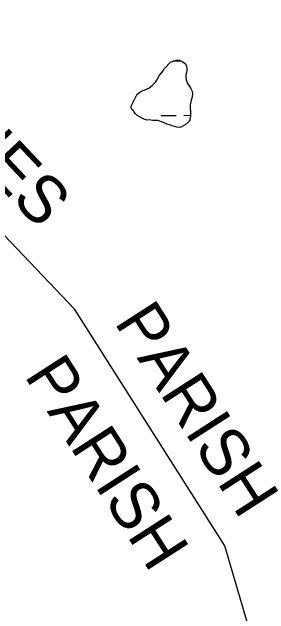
# Model space of a CAD drawing. Extents: x 3702978 to 3741108, y 397120 to 422907.
# Drawn here: x 3709024 to 3709567, y 408927 to 410197 of the extents above; entities that cross this region are included whole.
import ezdxf

# ---------------------------------------------------------------- set-up
doc = ezdxf.new("R2010")
doc.units = 0
for name, color, linetype in [('V-GRID-MAJR', 7, 'Continuous'), ('V-TOPO-BNDY', 7, 'Continuous'), ('V-TOPO-GNAM-IDEN', 7, 'Continuous'), ('V-TOPO-SHOR', 7, 'Continuous'), ('V-WETL-SWMP', 7, 'Continuous')]:
    doc.layers.add(name, color=color, linetype=linetype)

msp = doc.modelspace()

# ---------------------------------------------------------------- linework, layer by layer
at = {"layer": 'V-GRID-MAJR'}
msp.add_spline([(3707136.067, 408587.592), (3709783.788, 408618.69), (3715079.223, 408681.465), (3720374.649, 408745.011), (3725670.066, 408809.326), (3730965.473, 408874.412), (3736260.87, 408940.268), (3738908.566, 408973.485)], degree=3, dxfattribs=at)
at = {"layer": 'V-TOPO-BNDY'}
for p, q in [((3709157.052, 409569.789), (3708437.264, 410322.089)), ((3709474.211, 409070.798), (3709157.052, 409569.789)), ((3709593.302, 408661.849), (3709474.211, 409070.798))]:
    msp.add_line(p, q, dxfattribs=at)
at = {"layer": 'V-TOPO-SHOR'}
msp.add_lwpolyline([(3709275.193, 409997.449), (3709276.507, 410000.198), (3709289.023, 410024.275), (3709294.4, 410028.46), (3709300.47, 410031.977), (3709303.864, 410032.719), (3709313.328, 410036.978), (3709320.724, 410042.563), (3709327.415, 410049.498), (3709330.066, 410053.634), (3709332.061, 410056.396), (3709336.014, 410063.963), (3709340.685, 410069.499), (3709343.349, 410072.954), (3709346.657, 410078.465), (3709359.369, 410091.642), (3709365.452, 410094.477), (3709371.558, 410095.95), (3709378.383, 410095.391), (3709385.257, 410092.107), (3709390.781, 410088.117), (3709392.91, 410083.385), (3709393.652, 410079.991), (3709393.775, 410073.178), (3709393.155, 410069.759), (3709391.878, 410064.966), (3709391.27, 410060.866), (3709392.073, 410054.066), (3709393.497, 410050.684), (3709394.24, 410047.29), (3709397.026, 410043.933), (3709401.236, 410037.193), (3709404.059, 410031.792), (3709405.519, 410026.367), (3709405.58, 410022.96), (3709404.352, 410015.442), (3709403.063, 410011.33), (3709402.443, 410007.911), (3709401.129, 410005.162), (3709400.521, 410001.062), (3709400.681, 409992.205), (3709401.423, 409988.811), (3709401.643, 409976.549), (3709400.366, 409971.755), (3709399.746, 409968.337), (3709397.07, 409965.563), (3709390.367, 409959.309), (3709380.915, 409954.369), (3709377.521, 409953.627), (3709372.74, 409954.222), (3709367.947, 409955.499), (3709362.46, 409957.445), (3709357.654, 409959.403), (3709351.499, 409960.656), (3709344.625, 409963.94), (3709332.276, 409968.488), (3709321.376, 409968.293), (3709314.539, 409969.533), (3709309.77, 409969.447), (3709303.602, 409971.381), (3709296.728, 409974.665), (3709288.468, 409979.287), (3709285, 409982.632), (3709282.214, 409985.989), (3709280.802, 409988.69), (3709278.041, 409990.685)], close=True, dxfattribs=at)
at = {"layer": 'V-WETL-SWMP'}
for p, q in [((3709365.437, 410094.47), (3709379.934, 410094.65)), ((3709339.413, 409978.706), (3709371.411, 409979.103)), ((3709387.41, 409979.302), (3709401.59, 409979.478))]:
    msp.add_line(p, q, dxfattribs=at)
msp.add_lwpolyline([(3709275.193, 409997.449), (3709276.507, 410000.198), (3709289.023, 410024.275), (3709294.4, 410028.46), (3709300.47, 410031.977), (3709303.864, 410032.719), (3709313.328, 410036.978), (3709320.724, 410042.563), (3709327.415, 410049.498), (3709330.066, 410053.634), (3709332.061, 410056.396), (3709336.014, 410063.963), (3709340.685, 410069.499), (3709343.349, 410072.954), (3709346.657, 410078.465), (3709359.369, 410091.642), (3709365.452, 410094.477), (3709371.558, 410095.95), (3709378.383, 410095.391), (3709385.257, 410092.107), (3709390.781, 410088.117), (3709392.91, 410083.385), (3709393.652, 410079.991), (3709393.775, 410073.178), (3709393.155, 410069.759), (3709391.878, 410064.966), (3709391.27, 410060.866), (3709392.073, 410054.066), (3709393.497, 410050.684), (3709394.24, 410047.29), (3709397.026, 410043.933), (3709401.236, 410037.193), (3709404.059, 410031.792), (3709405.519, 410026.367), (3709405.58, 410022.96), (3709404.352, 410015.442), (3709403.063, 410011.33), (3709402.443, 410007.911), (3709401.129, 410005.162), (3709400.521, 410001.062), (3709400.681, 409992.205), (3709401.423, 409988.811), (3709401.643, 409976.549), (3709400.366, 409971.755), (3709399.746, 409968.337), (3709397.07, 409965.563), (3709390.367, 409959.309), (3709380.915, 409954.369), (3709377.521, 409953.627), (3709372.74, 409954.222), (3709367.947, 409955.499), (3709362.46, 409957.445), (3709357.654, 409959.403), (3709351.499, 409960.656), (3709344.625, 409963.94), (3709332.276, 409968.488), (3709321.376, 409968.293), (3709314.539, 409969.533), (3709309.77, 409969.447), (3709303.602, 409971.381), (3709296.728, 409974.665), (3709288.468, 409979.287), (3709285, 409982.632), (3709282.214, 409985.989), (3709280.802, 409988.69), (3709278.041, 409990.685)], close=True, dxfattribs=at)

# ---------------------------------------------------------------- texts
at = {"layer": 'V-TOPO-GNAM-IDEN'}
for s, rotation, p in [('PLAQUEMINES', 313.352237, (3708419.471, 410439.329)), ('PARISH', 302.749532, (3709239.106, 409542.652)), ('PARISH', 302.749532, (3709048.942, 409430.098))]:
    msp.add_text(s, height=99.9998, rotation=rotation, dxfattribs=at).set_placement(p)

doc.saveas('drawing.dxf')
